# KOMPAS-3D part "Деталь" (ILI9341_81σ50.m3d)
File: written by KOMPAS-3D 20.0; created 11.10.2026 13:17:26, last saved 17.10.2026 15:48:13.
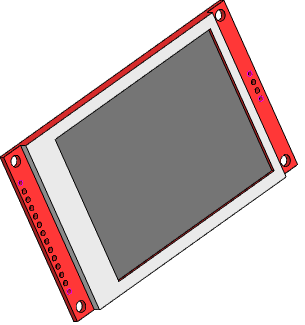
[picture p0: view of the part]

Document properties: Полное имя файла: D:\myProjects\Progect_esp32\box_compas\монитор\ILI9341_81х50.m3d

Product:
- Part/product: Деталь
    Масса: 0.0948715

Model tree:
1. Эскиз:1
2. Элемент выдавливания:1
     Расстояние 1 = 1.6
3. Эскиз:2  (with: Элемент выдавливания:1)
4. Элемент выдавливания:2
     Расстояние 2 = 1.6
5. Массив по сетке:1  (with: Элемент выдавливания:2, Эскиз:2)  (4 pattern instances)
     Шаг 1 = 44.2; Угол раствора = -90; Шаг 2 = 75.9
6. Эскиз:3  (with: Элемент выдавливания:1, Элемент выдавливания:2)
7. Элемент выдавливания:3
     Расстояние 1 = 2.35
8. Эскиз:4  (with: Элемент выдавливания:3, Элемент выдавливания:1)
9. Элемент выдавливания:4
     Расстояние 2 = 1
10. Эскиз:5  (with: Элемент выдавливания:1)
11. Элемент выдавливания:5
     Расстояние 2 = 1.6
12. Массив по сетке:2  (with: Элемент выдавливания:5, Эскиз:5)  (14 pattern instances)
     Шаг 1 = 2.54; Угол раствора = 90
13. Эскиз:6  (with: Элемент выдавливания:1)
14. Элемент выдавливания:6
     Расстояние 2 = 1.6
15. Массив по сетке:3  (with: Элемент выдавливания:6, Эскиз:6)  (4 pattern instances)
     Шаг 1 = 2.54; Угол раствора = 90
16. Эскиз:7  (with: Элемент выдавливания:1, Элемент выдавливания:6, Элемент выдавливания:4, Элемент выдавливания:5, Элемент выдавливания:3)

Referenced files in D:\myProjects\Progect_esp32\box_compas\: psb TFT 81_7x50.png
